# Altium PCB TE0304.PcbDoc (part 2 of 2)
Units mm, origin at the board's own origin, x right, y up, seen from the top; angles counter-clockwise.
Board outline 115 x 73 mm, 4 copper layers (L 01 (Top), L 02, L 03, L 04 (Bot)), stack 1.564 mm thick; 95 components, 174 nets, 553 pads, 126 vias.
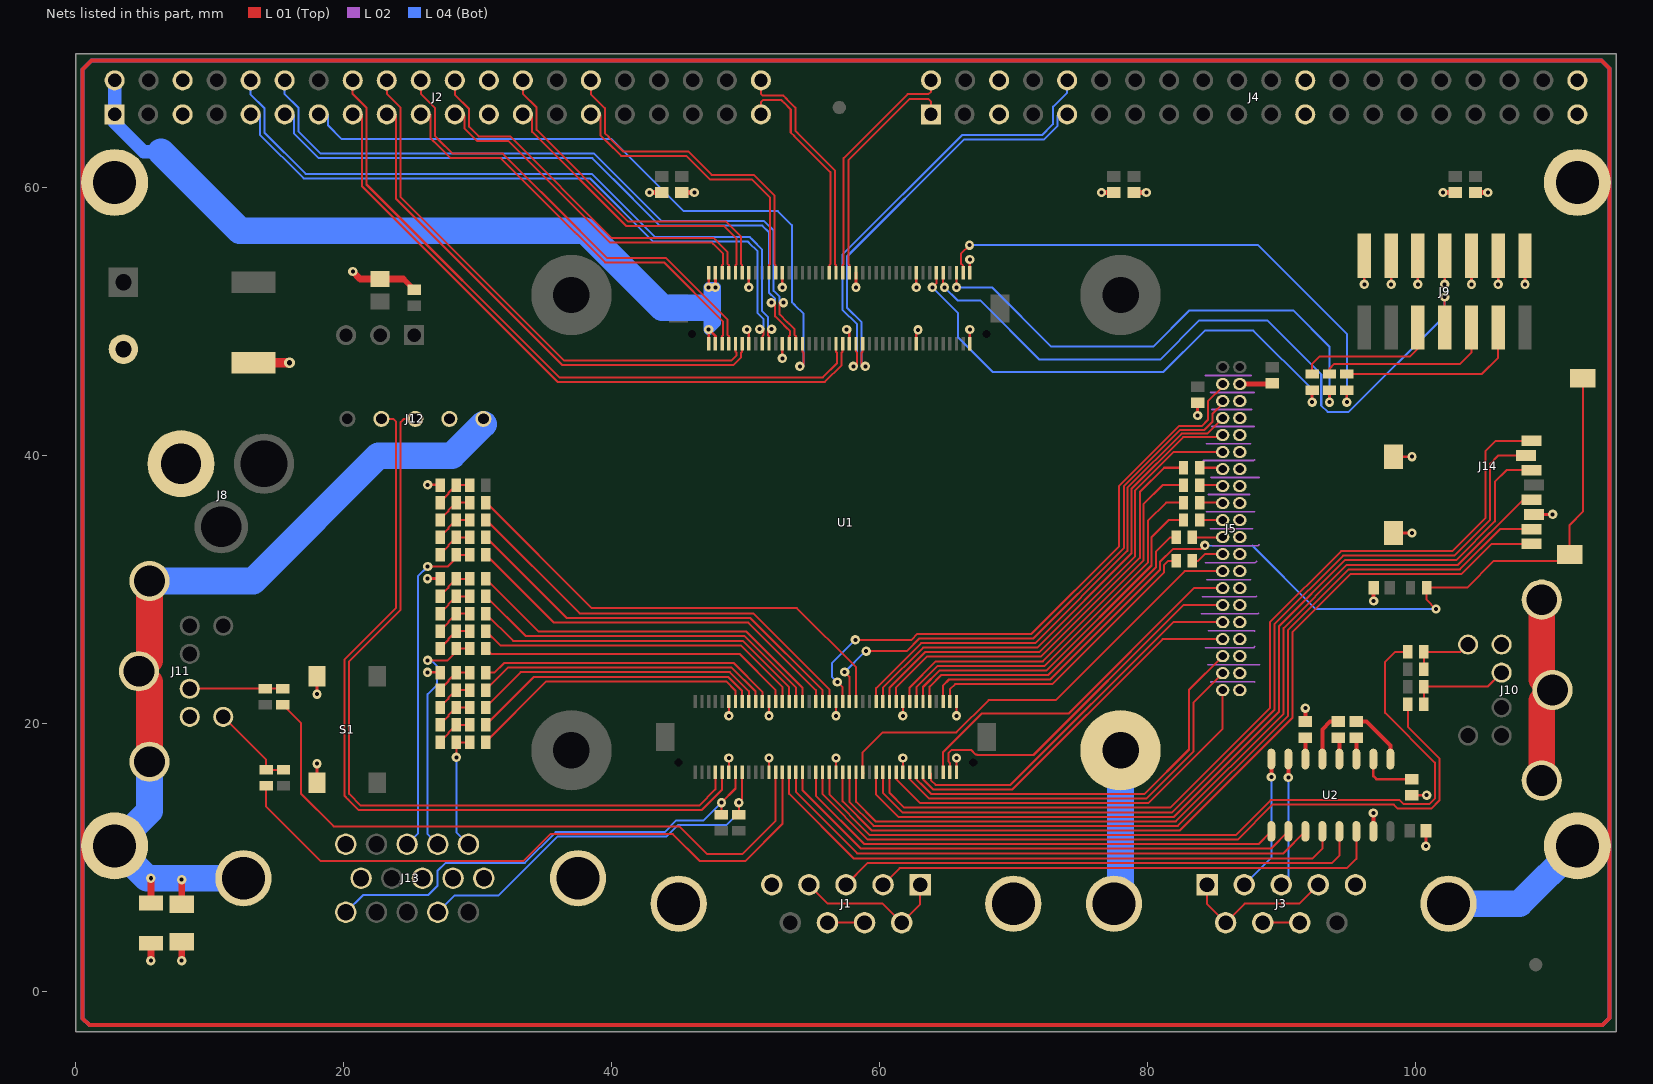
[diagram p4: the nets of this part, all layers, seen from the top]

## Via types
v1: diameter 0.7, hole 0.3, L 01 (Top) to L 04 (Bot), 124 vias
v2: diameter 0.8, hole 0.4, L 01 (Top) to L 04 (Bot), 2 vias

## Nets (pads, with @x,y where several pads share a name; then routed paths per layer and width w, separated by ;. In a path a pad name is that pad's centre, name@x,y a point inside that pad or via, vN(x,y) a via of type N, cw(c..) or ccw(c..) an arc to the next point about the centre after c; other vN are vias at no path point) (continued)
B0_L20_P: J2.13 U1.J4-29 | length 52.4
  L 01 (Top) w0.15: v1(54.05,46.675) 54.33,46.675 54.33,47.695 54.25,47.775 U1.J4-29@54.25,48.35
  L 04 (Bot) w0.15: J2.13@18.13,65.48 18.82,65.48 18.825,65.485 18.825,65.48 18.825,64.659 19.824,63.66 39.984,63.66 43.085,60.559 43.184,60.46 45.384,58.26 52.409,58.26 53.46,57.209 53.46,51.459 53.585,51.334 53.684,51.235 54.33,50.589 54.33,46.675 v1(54.05,46.675)
B0_L21_N: J2.29 U1.J4-20 | length 22.5
  L 01 (Top) w0.15: J2.29@38.45,65.48 39.115,65.48 39.16,65.435 39.16,63.934 39.535,63.559 39.634,63.46 40.709,62.385 45.584,62.385 47.334,60.635 50.459,60.635 51.83,59.264 51.83,54.305 51.75,54.225 U1.J4-20@51.75,53.65
B0_L21_P: J2.30 U1.J4-22 | length 24.8
  L 01 (Top) w0.15: J2.30@38.45,68.02 38.45,67 39.5,65.95 39.5,64.075 39.775,63.8 39.875,63.7 40.85,62.725 45.725,62.725 47.475,60.975 50.6,60.975 52.17,59.405 52.17,54.305 52.25,54.225 U1.J4-22@52.25,53.65
B0_L23_N: J2.11 U1.J4-25 | length 50.2
  L 01 (Top) w0.15: v1(51.93,51.429) 52.21,51.429 52.21,50.409 52.885,49.734 52.984,49.635 53.33,49.289 53.33,49.005 53.25,48.925 U1.J4-25@53.25,48.35
  L 04 (Bot) w0.15: J2.11@15.59,65.48 16.235,65.48 16.29,65.425 16.29,64.05 16.59,63.75 16.69,63.65 18.13,62.21 38.559,62.21 41.56,59.209 41.659,59.11 43.594,57.175 51.25,57.175 51.75,56.675 51.75,52.175 52.21,51.715 52.21,51.429 v1(51.93,51.429)
B0_L23_P: J2.12 U1.J4-27 | length 52.5
  L 01 (Top) w0.15: v1(52.83,51.429) 52.55,51.429 52.55,50.55 53.125,49.975 53.225,49.875 53.67,49.43 53.67,49.005 53.75,48.925 U1.J4-27@53.75,48.35
  L 04 (Bot) w0.15: J2.12@15.59,68.02 15.59,67 16.63,65.96 16.63,64.191 16.831,63.99 16.93,63.891 18.271,62.55 38.7,62.55 41.8,59.45 41.9,59.35 43.735,57.515 51.391,57.515 52.09,56.816 52.09,52.316 52.55,51.856 52.55,51.429 v1(52.83,51.429)
B0_L24_N: J2.9 U1.J4-17 | length 50.4
  L 01 (Top) w0.15: U1.J4-17@51.25,48.35 51.25,48.925 51.33,49.005 v1@51.33,49.45
  L 04 (Bot) w0.15: J2.9@13.05,65.48 13.735,65.48 13.74,65.475 13.74,63.975 17.005,60.71 38.384,60.71 43.119,55.975 50.175,55.975 50.25,55.9 50.9,55.25 50.9,50.65 51,50.55 51.05,50.5 51.33,50.22 51.33,49.45 v1(51.05,49.45)
B0_L24_P: J2.10 U1.J4-19 | length 52.6
  L 01 (Top) w0.15: v1@51.67,49.45 51.67,49.005 51.75,48.925 U1.J4-19@51.75,48.35
  L 04 (Bot) w0.15: J2.10@13.05,68.02 13.05,66.965 14.08,65.935 14.08,64.116 17.146,61.05 38.525,61.05 43.26,56.315 50.316,56.315 50.415,56.215 50.49,56.141 51.24,55.391 51.24,50.791 51.29,50.741 51.67,50.361 51.67,49.45 v1(51.95,49.45)
B1: R33.2 U1.J5-50 | length 35.4
  L 01 (Top) w0.15: R33.2@30.712,36.525 30.612,36.525 30.618,36.518 38.527,28.61 53.832,28.61 58.25,24.192 U1.J5-50@58.25,21.65
B2: R27.2 U1.J5-42 | length 31.8
  L 01 (Top) w0.15: R27.2@30.612,35.225 30.618,35.218 37.617,28.22 50.58,28.22 56.25,22.55 U1.J5-42@56.25,21.65
B3: R20.2 U1.J5-40 | length 30.7
  L 01 (Top) w0.15: R20.2@30.612,33.925 30.618,33.918 36.657,27.88 50.351,27.88 55.75,22.481 U1.J5-40@55.75,21.65
B3_L01_N: J2.20 U1.J4-7 | length 34
  L 01 (Top) w0.15: J2.20@25.75,68.02 25.75,67.025 26.8,65.975 26.8,63.875 26.975,63.7 27.075,63.6 28.125,62.55 31.875,62.55 37.525,56.9 37.625,56.8 39.65,54.775 44.05,54.775 48.67,50.155 48.67,49.005 48.75,48.925 U1.J4-7@48.75,48.35
B3_L01_P: J2.19 U1.J4-5 | length 31.7
  L 01 (Top) w0.15: J2.19@25.75,65.48 26.45,65.48 26.46,65.49 26.46,65.48 26.46,63.734 26.735,63.459 26.834,63.36 27.984,62.21 31.734,62.21 37.285,56.659 37.384,56.56 39.509,54.435 43.909,54.435 48.33,50.014 48.33,49.005 48.25,48.925 U1.J4-5@48.25,48.35
B3_L02_N: J2.17 U1.J4-11 | length 39.1
  L 01 (Top) w0.15: J2.17@23.21,65.48 23.845,65.48 23.9,65.425 23.9,59.169 36.294,46.775 49.1,46.775 49.2,46.875 49.3,46.975 49.67,47.345 49.67,47.695 49.75,47.775 U1.J4-11@49.75,48.35
B3_L02_P: J2.18 U1.J4-9 | length 40.3
  L 01 (Top) w0.15: J2.18@23.21,68.02 23.21,67.015 24.24,65.985 24.24,59.31 36.435,47.115 48.959,47.115 49.059,47.215 49.33,47.486 49.33,47.695 49.25,47.775 U1.J4-9@49.25,48.35
B3_L03_N: J2.25 U1.J4-10 | length 23.2
  L 01 (Top) w0.15: J2.25@33.37,65.48 34.05,65.48 34.06,65.49 34.06,65.48 34.06,64.184 41.109,57.135 48.409,57.135 49.33,56.214 49.33,54.305 49.25,54.225 U1.J4-10@49.25,53.65
B3_L03_P: J2.26 U1.J4-12 | length 25.4
  L 01 (Top) w0.15: J2.26@33.37,68.02 33.37,67.03 34.4,66 34.4,64.325 41.25,57.475 48.55,57.475 49.67,56.355 49.67,54.305 49.75,54.225 U1.J4-12@49.75,53.65
B3_L07_N: J2.22 U1.J4-8 | length 28.7
  L 01 (Top) w0.15: J2.22@28.29,68.02 28.29,66.96 29.35,65.9 29.35,64.575 29.375,64.55 29.475,64.45 30.075,63.85 32.425,63.85 40.025,56.25 47.625,56.25 47.725,56.15 47.825,56.05 48.67,55.205 48.67,54.305 48.75,54.225 U1.J4-8@48.75,53.65
B3_L07_P: J2.21 U1.J4-6 | length 26.4
  L 01 (Top) w0.15: J2.21@28.29,65.48 28.97,65.48 29.01,65.44 29.01,64.434 29.135,64.309 29.234,64.21 29.934,63.51 32.284,63.51 39.884,55.91 47.484,55.91 ; 47.485,55.909 47.584,55.81 48.33,55.064 48.33,54.305 48.25,54.225 U1.J4-6@48.25,53.65
B4: R14.2 U1.J5-38 | length 29.7
  L 01 (Top) w0.15: R14.2@30.612,32.625 30.618,32.618 35.697,27.54 50.21,27.54 55.25,22.5 U1.J5-38@55.25,21.65
BLUE: J13.3 R14.1 R17.1 | length 24.8
  L 01 (Top) w0.15: v1(26.262,31.725) 27.762,31.725 R17.1@28.424,32.387 ; R17.1@28.4,32.6 R14.1@29.4,32.6 R14.1@29.4,32.575
  L 04 (Bot) w0.15: J13.3@24.73,10.99 25.525,11.785 25.525,30.988 v1(26.262,31.725)
DOUT0: J5.30 U1.J5-60 | length 36.1
  L 01 (Top) w0.15: U1.J5-60@60.75,21.65 60.75,22.681 63.399,25.33 71.914,25.33 79.087,32.502 79.087,37.409 81.947,40.27 J5.30@85.63,40.27
DOUT1: J5.32 U1.J5-58 | length 37
  L 01 (Top) w0.15: U1.J5-58@60.25,21.65 60.25,22.662 63.258,25.67 71.773,25.67 78.817,32.713 78.817,37.521 82.676,41.38 85.47,41.38 J5.32@85.63,41.54 J5.32@85.609,41.54
DOUT2: J5.34 U1.J5-56 | length 38
  L 01 (Top) w0.15: U1.J5-56@59.75,21.65 59.75,22.642 63.118,26.01 71.633,26.01 78.51,32.887 78.51,37.596 82.564,41.65 84.47,41.65 J5.34@85.63,42.81
DOUT3: J5.38 U1.J5-46 | length 44.6
  L 01 (Top) w0.15: v1(56.85,23.1) 57.25,22.7 U1.J5-46@57.25,21.65 ; v1(58.2,26.25) 62.396,26.25 62.836,26.69 71.351,26.69 77.9,33.239 77.9,37.75 82.35,42.2 84.058,42.2 84.525,42.667 84.525,44.057 85.63,45.162 J5.38@85.63,45.35
  L 04 (Bot) w0.15: v1(56.85,23.1) 56.45,23.5 56.45,24.5 v1(58.2,26.25)
DOUT4: J5.36 U1.J5-48 | length 42.1
  L 01 (Top) w0.15: v1(57.4,23.85) 57.75,23.5 U1.J5-48@57.75,21.65 ; v1(59,25.4) 62.027,25.4 62.977,26.35 71.492,26.35 78.24,33.098 78.24,37.708 82.462,41.93 84.269,41.93 84.865,42.526 84.865,43.127 85.63,43.892 J5.36@85.63,44.08
  L 04 (Bot) w0.15: v1(57.4,23.85) 58.95,25.4 v1(59,25.4)
DOUT5: J5.2 U1.J5-61 | length 30.8
  L 01 (Top) w0.15: U1.J5-61@61.25,16.35 61.25,15.85 63.045,14.055 80.064,14.055 85.63,19.621 J5.2@85.63,22.49
DOUT6: J5.4 U1.J5-65 | length 30.5
  L 01 (Top) w0.15: U1.J5-65@62.25,16.35 62.25,15.85 63.705,14.395 79.923,14.395 83.45,17.922 83.45,21.58 J5.4@85.63,23.76
DOUT7: J5.6 U1.J5-67 | length 30.7
  L 01 (Top) w0.15: U1.J5-67@62.75,16.35 62.75,15.85 63.3,15.3 63.319,15.3 63.884,14.735 79.782,14.735 83.11,18.063 83.11,22.51 J5.6@85.63,25.03
DOUT8: J5.8 U1.J5-69 | length 27.9
  L 01 (Top) w0.15: U1.J5-69@63.25,16.35 63.25,15.85 64.025,15.075 69.925,15.075 81.15,26.3 J5.8@85.63,26.3
DOUT9: J5.10 U1.J5-71 | length 27.6
  L 01 (Top) w0.15: U1.J5-71@63.75,16.35 63.86,16.24 63.86,15.74 64.185,15.415 69.784,15.415 81.939,27.57 J5.10@85.63,27.57
EXPOSURE: R47.2 U1.J5-72 | length 24.8
  L 01 (Top) w0.15: U1.J5-72@63.75,21.65 63.75,22.75 64.63,23.63 72.618,23.63 80.64,31.652 80.64,32.84 81.7,33.9 R47.2@82.15,33.9
FGND: C15.1 H1.1 H2.1 H3.1 H4.1 J1.S1 J1.S2 J3.S1 J3.S2 J10.S1 J10.S2 J10.S3 J11.S1 J11.S2 J11.S3 J12.5 J13.S1 J13.S2 R4.1 U1.2 | length 844.1
  L 01 (Top) w0.3: 0.5,-2.008 0.5,10.87 0.5,60.4 0.5,68.825 1.175,69.5 113.9,69.5 114.5,68.9 114.5,60.4 114.5,10.87 114.5,-2 113.992,-2.508 1,-2.508 0.5,-2.008
  L 01 (Top) w0.5: R4.1@5.6,6.6 v1(5.6,8.45) ; C15.1@7.9,6.5 v1(7.9,8.35)
  L 01 (Top) w2: J11.S3@5.5,17.15 5.5,23.1 J11.S2@4.7,23.9 5.5,24.7 J11.S1@5.5,30.65 ; J10.S1@109.45,15.75 109.45,21.7 J10.S2@110.25,22.5 109.45,23.3 J10.S3@109.45,29.25
  L 04 (Bot) w0.3: 0.5,-2.008 0.5,10.87 0.5,60.4 0.5,68.825 1.175,69.5 113.9,69.5 114.5,68.9 114.5,60.4 114.5,10.87 114.5,-2 113.992,-2.508 1,-2.508 0.5,-2.008
  L 04 (Bot) w2: H1.1@2.89,10.87 5.31,8.45 v1(5.6,8.45) 7.9,8.45 J13.S2@12.505,8.45 ; H1.1@2.995,10.975 5.5,13.48 J11.S3@5.5,17.15 ; J11.S1@5.5,30.65 13.241,30.65 22.591,40 28.074,40 J12.5@30.43,42.356 ; J3.S2@77.505,6.55 78,7.045 U1.2@78,18 ; J3.S1@102.495,6.55 107.79,6.55 H2.1@112.11,10.87
FPGA_RXD-DCE: U1.J5-29 U2.12 | length 45
  L 01 (Top) w0.15: U1.J5-29@53.25,16.35 53.25,14.75 58.06,9.94 92.34,9.94 93.065,10.665 U2.12@93.065,11.95
FPGA_RXD-DTE: U1.J5-37 U2.9 | length 37.6
  L 01 (Top) w0.15: U1.J5-37@55.25,16.35 55.25,14.625 58.88,10.995 88.3,10.995 U2.9@89.255,11.95
FPGA_TXD-DCE: U1.J5-31 U2.11 | length 42.1
  L 01 (Top) w0.15: U1.J5-31@53.75,16.35 53.75,14.9 58.335,10.315 90.164,10.315 91.795,11.946 U2.11@91.795,11.95
FPGA_TXD-DTE: U1.J5-33 U2.10 | length 39.9
  L 01 (Top) w0.15: U1.J5-33@54.25,16.35 54.25,15.025 58.62,10.655 89.234,10.655 90.525,11.946 U2.10@90.525,11.95
FRAME_VALID: J5.14 U1.J5-75 | length 27.5
  L 01 (Top) w0.15: U1.J5-75@64.75,16.35 64.75,17.875 67.625,20.75 74.119,20.75 83.479,30.11 J5.14@85.63,30.11
G0: R40.2 U1.J5-34 | length 28.1
  L 01 (Top) w0.15: R40.2@30.6,30.825 30.612,30.812 34.565,26.86 50.072,26.86 54.25,22.682 U1.J5-34@54.25,21.65
G1: R34.2 U1.J5-32 | length 27
  L 01 (Top) w0.15: R34.2@30.6,29.525 30.612,29.512 33.605,26.52 49.932,26.52 53.75,22.702 U1.J5-32@53.75,21.65
G2: R28.2 U1.J5-30 | length 26
  L 01 (Top) w0.15: R28.2@30.6,28.225 30.612,28.212 32.645,26.18 49.791,26.18 53.25,22.721 U1.J5-30@53.25,21.65
G3: R21.2 U1.J5-28 | length 25
  L 01 (Top) w0.15: R21.2@30.6,26.925 30.612,26.912 31.685,25.84 49.65,25.84 52.75,22.74 U1.J5-28@52.75,21.65
G4: R15.2 U1.J5-26 | length 23.8
  L 01 (Top) w0.15: R15.2@30.6,25.625 30.612,25.612 31.025,25.2 49.55,25.2 52.25,22.5 U1.J5-26@52.25,21.65
GCLK_L11_N: J4.2 U1.J4-42 | length 18
  L 01 (Top) w0.15: U1.J4-42@57.25,53.65 57.25,54.225 57.33,54.305 57.33,62.211 62.109,66.99 63.65,66.99 63.85,67.19 J4.2@63.85,68.02
GCLK_L11_P: J4.1 U1.J4-44 | length 17.6
  L 01 (Top) w0.15: U1.J4-44@57.75,53.65 57.75,54.225 57.67,54.305 57.67,62.07 62.25,66.65 63.63,66.65 63.85,66.43 J4.1@63.85,65.48
GCLK_L12_N: J4.9 U1.J4-47 | length 32.2
  L 01 (Top) w0.15: U1.J4-47@58.75,48.35 58.75,47.775 58.67,47.695 58.67,46.675 v1(58.95,46.675)
  L 04 (Bot) w0.15: v1(58.95,46.675) 58.67,46.675 58.67,49.955 57.575,51.05 57.575,51.9 57.575,54.875 66.3,63.6 72.275,63.6 73.1,64.425 73.2,64.525 73.3,64.625 73.3,65.4 73.38,65.48 J4.9@74.01,65.48
GCLK_L12_P: J4.10 U1.J4-45 | length 34.5
  L 01 (Top) w0.15: v1(58.05,46.675) 58.33,46.675 58.33,47.695 58.25,47.775 U1.J4-45@58.25,48.35
  L 04 (Bot) w0.15: v1(58.05,46.675) 58.33,46.675 58.33,49.814 57.235,50.909 57.235,51.9 57.235,55.016 66.159,63.94 72.134,63.94 72.86,64.666 72.959,64.765 ; 72.96,64.766 72.96,66.06 74.01,67.11 J4.10@74.01,68.02
GCLK_L13_N: J2.15 U1.J4-41 | length 50
  L 01 (Top) w0.15: J2.15@20.67,65.48 21.345,65.48 21.36,65.465 21.36,60.109 35.959,45.51 55.916,45.51 57.17,46.764 57.17,47.695 57.25,47.775 U1.J4-41@57.25,48.35
GCLK_L13_P: J2.16 U1.J4-39 | length 51.2
  L 01 (Top) w0.15: J2.16@20.67,68.02 20.67,67.005 21.7,65.975 21.7,60.25 36.1,45.85 55.775,45.85 56.83,46.905 56.83,47.695 56.75,47.775 U1.J4-39@56.75,48.35
GCLK_L14_N: J2.39 U1.J4-38 | length 17
  L 01 (Top) w0.15: J2.39@51.15,65.48 51.15,66.4 51.3,66.55 52.675,66.55 52.75,66.475 52.85,66.375 53.375,65.85 53.375,64.125 53.625,63.875 53.725,63.775 56.33,61.17 56.33,54.305 56.25,54.225 U1.J4-38@56.25,53.65
GCLK_L14_P: J2.40 U1.J4-40 | length 17.6
  L 01 (Top) w0.15: J2.40@51.15,68.02 51.15,67.04 51.3,66.89 52.816,66.89 52.991,66.715 53.09,66.616 53.715,65.991 53.715,64.266 53.866,64.115 53.965,64.016 56.67,61.311 56.67,54.305 56.75,54.225 U1.J4-40@56.75,53.65
GND: C1.1 C2.2 C3.2 C4.2 C5.2 C6.2 C9.2 C10.2 C11.2 C12.2 C13.2 C14.2 C15.2 C16.2 C17.2 D1.2 J1.5 J2.5 J2.6 J2.23 J2.24 J3.5 J4.5 J4.6 J4.23 J4.24 J4.39 J4.40 J5.1 J5.3 J5.5 J5.7 J5.9 J5.11 J5.13 J5.15 J5.17 J5.19 J5.21 J5.23 J5.25 J5.27 J5.29 J5.31 J5.33 J5.35 J5.37 J7.2 J8.3 J9.1 J9.3 J9.5 J9.7 J9.9 J9.11 J9.13 J10.3 J11.3 J12.4 J13.5 J13.6 J13.7 J13.8 J13.10 J14.6 J14.10 R4.2 R42.2 R43.2 R44.2 S1.2 U1.J4-13 U1.J4-14 U1.J4-23 U1.J4-24 U1.J4-43 U1.J4-46 U1.J4-63 U1.J4-64 U1.J4-79 U1.J4-80 U1.J5-11 U1.J5-12 U1.J5-23 U1.J5-24 U1.J5-43 U1.J5-44 U1.J5-63 U1.J5-64 U1.J5-79 U1.J5-80 U2.15 | length 138.3
  L 01 (Top) w0.15: U1.J5-11@48.75,16.35 v1(48.75,17.425) ; v1(48.75,20.575) U1.J5-12@48.75,21.65 ; U1.J5-23@51.75,16.35 v1(51.75,17.425) ; v1(51.75,20.575) U1.J5-24@51.75,21.65 ; U1.J5-43@56.75,16.35 v1(56.75,17.425) ; v1(56.75,20.575) U1.J5-44@56.75,21.65 ; U1.J5-63@61.75,16.35 v1(61.75,17.425) ; v1(61.75,20.575) U1.J5-64@61.75,21.65 ; U1.J5-79@65.75,16.35 v1(65.75,17.425) ; v1(65.75,20.575) U1.J5-80@65.75,21.65
  L 01 (Top) w0.2: S1.2@18,15.575 v1(18,17) ; v1(18,22.2) S1.2@18,23.525 ; v1(26.25,23.825) R44.2@27.212,23.825 ; v1(26.25,30.825) R43.2@27.212,30.825 ; v1(26.262,37.825) R42.2@27.224,37.825 ; v1(50.1,49.425) 50.25,49.275 U1.J4-13@50.25,48.35 ; v1(50.25,52.575) U1.J4-14@50.25,53.65 ; v1(52.75,47.275) U1.J4-23@52.75,48.35 ; v1(52.75,52.575) U1.J4-24@52.75,53.65 ; U1.J4-43@57.75,48.35 v1@57.75,49.425 ; v1(58.25,52.575) U1.J4-46@58.25,53.65 ; U1.J4-63@62.75,48.35 v1@62.75,49.425 ; v1(62.75,52.575) U1.J4-64@62.75,53.65 ; U1.J4-79@66.75,48.35 v1(66.75,49.425) ; U1.J4-80@66.75,53.575 v1(66.75,54.65) ; v1(96.2,52.8) J9.13@96.2,54.935 ; v1(98.2,52.8) J9.11@98.2,54.935 ; J14.10@98.375,34.225 v1(99.765,34.225) ; J14.10@98.375,39.925 v1(99.765,39.925) ; C5.2@99.75,14.65 v1(100.85,14.65) ; v1(100.2,52.8) J9.9@100.2,54.935 ; v1(100.8,10.85) C6.2@100.8,12 ; v1(102.2,52.8) J9.7@102.2,54.935 ; v1(104.2,52.8) J9.5@104.2,54.935 ; v1(106.2,52.8) J9.3@106.2,54.935 ; v1(108.2,52.8) J9.1@108.2,54.935 ; J14.6@108.875,35.615 v1(110.265,35.615)
  L 01 (Top) w0.25: v1(83.75,43.005) C16.2@83.75,43.95
  L 01 (Top) w0.3: C11.2@91.8,20.15 v1(91.8,21.15) ; U2.15@96.875,11.95 v1(96.875,13.325) ; v1(96.9,29.15) C17.2@96.9,30.15
  L 01 (Top) w0.4: 24.45,53.2 C2.2@25.25,52.4 ; v1(42.825,59.65) C3.2@43.75,59.65 ; C4.2@45.25,59.65 v1(46.175,59.65) ; v1(76.575,59.65) C10.2@77.5,59.65 ; C9.2@79,59.65 v1(79.925,59.65) ; J5.37@86.955,45.405 J5.37@86.9,45.35 89.26,45.35 C12.2@89.315,45.405 ; v1(102.075,59.65) C13.2@103,59.65 ; C14.2@104.5,59.65 v1(105.425,59.65)
  L 01 (Top) w0.5: v1(5.6,2.3) R4.2@5.6,3.6 ; v1(7.9,2.3) C15.2@7.9,3.7 ; v1(20.675,53.75) 21.225,53.2 C1.1@22.7,53.2 24.45,53.2
  L 01 (Top) w0.7: D1.2@13.25,46.95 v2(15.95,46.95)
  L 02 w0.12: 84.04,28.21 88.26,28.21 88.3,28.25 ; 84.12,29.48 88.13,29.48 88.15,29.5 ; 84.19,39.64 87.955,39.64 88.015,39.7 ; 84.33,25.67 87.935,25.67 88.015,25.75 ; 84.33,32.02 88.07,32.02 88.15,32.1 ; 84.34,45.99 87.74,45.99 87.75,46 ; 84.4,40.9 87.7,40.9 ; 84.42,35.82 87.995,35.82 88.015,35.8 ; 84.45,30.75 87.7,30.75 ; 84.515,24.4 88.4,24.4 ; 84.545,26.93 87.985,26.93 88.015,26.9 ; 84.565,37.1 87.65,37.1 ; 84.7,34.55 87.85,34.55 ; 84.7,44.75 84.73,44.72 87.985,44.72 ; 84.75,23.1 84.77,23.12 87.995,23.12 88.015,23.1 ; 84.75,38.4 84.78,38.37 88.37,38.37 ; 84.8,42.2 84.82,42.18 87.995,42.18 ; 84.8,43.45 87.8,43.45 ; 84.871,33.29 88.29,33.29 88.35,33.35
  other v1: 95.2,8.15 62.875,49.4 57.55,49.425
GREEN: J13.2 R15.1 R18.1 | length 18.5
  L 01 (Top) w0.15: v1(26.262,24.725) 27.762,24.725 28.412,25.375 R18.1@28.412,25.6 ; R18.1@28.4,25.6 R18.1@28.412,25.6 ; R15.1@29.4,25.575 R15.1@29.4,25.6 R18.1@28.412,25.6
  L 04 (Bot) w0.15: v1(26.262,24.725) 26.525,24.725 26.975,24.275 26.975,22.913 26.262,22.2 26.262,11.748 J13.2@27.02,10.99
LINE_VALID: J5.12 U1.J5-77 | length 26.9
  L 01 (Top) w0.15: U1.J5-77@65.25,16.35 65.25,17.055 65.135,17.17 65.135,17.779 65.396,18.04 66.835,18.04 67.19,17.685 67.265,17.685 67.3,17.65 71.5,17.65 82.69,28.84 J5.12@85.63,28.84
NetC5_1: C5.1 U2.2 | length 4.2
  L 01 (Top) w0.2: U2.2@96.875,17.35 96.875,16.075 97.1,15.85 C5.1@99.75,15.85
NetC7_1: C7.1 U2.4 | length 1.5
  L 01 (Top) w0.3: U2.4@94.335,17.35 C7.1@94.335,18.865
NetC7_2: C7.2 U2.5 | length 3.6
  L 01 (Top) w0.3: U2.5@93.065,17.35 93.065,19.565 93.65,20.15 C7.2@94.25,20.15
NetC8_1: C8.1 U2.1 | length 4.3
  L 01 (Top) w0.3: C8.1@95.6,20.15 96.35,20.15 98.145,18.355 U2.1@98.145,17.35
NetC8_2: C8.2 U2.3 | length 1.6
  L 01 (Top) w0.3: U2.3@95.605,17.35 C8.2@95.605,18.945
NetC11_1: C11.1 U2.6 | length 1.6
  L 01 (Top) w0.3: U2.6@91.8,17.355 C11.1@91.8,18.95
NetJ1_1: J1.1 J1.4 J1.6 | length 11.5
  L 01 (Top) w0.15: J1.4@54.73,7.97 56.15,6.55 60.235,6.55 J1.6@61.655,5.13 63.04,6.515 J1.1@63.04,7.97
NetJ1_7: J1.7 J1.8 | length 2.8
  L 01 (Top) w0.15: J1.8@56.115,5.13 J1.7@58.885,5.13
NetJ3_1: J3.1 J3.4 J3.6 | length 11.5
  L 01 (Top) w0.15: J3.1@84.46,7.97 84.46,6.515 J3.6@85.845,5.13 87.265,6.55 91.35,6.55 J3.4@92.77,7.97
NetJ3_7: J3.7 J3.8 | length 2.8
  L 01 (Top) w0.15: J3.7@88.615,5.13 J3.8@91.385,5.13
NetJ5_18: J5.18 R46.1 | length 2.5
  L 01 (Top) w0.15: R46.1@83.35,32.15 83.8,32.15 84.3,32.65 J5.18@85.63,32.65
NetJ5_20: J5.20 R47.1 | length 2.3
  L 01 (Top) w0.15: R47.1@83.35,33.9 85.61,33.9 J5.20@85.63,33.92
NetJ5_22: J5.22 R48.1 | length 1.7
  L 01 (Top) w0.15: R48.1@83.9,35.2 85.62,35.2 J5.22@85.63,35.19
NetJ5_24: J5.24 R49.1 | length 1.7
  L 01 (Top) w0.15: R49.1@83.9,36.5 85.59,36.5 J5.24@85.63,36.46
NetJ5_26: J5.26 R50.1 | length 1.8
  L 01 (Top) w0.15: R50.1@83.9,37.8 85.56,37.8 J5.26@85.63,37.73
NetJ5_28: J5.28 R51.1 | length 1.8
  L 01 (Top) w0.15: R51.1@83.9,39.1 85.53,39.1 J5.28@85.63,39
NetJ10_1: J10.1 R6.2 R7.1 | length 7.5
  L 01 (Top) w0.15: R7.1@100.65,21.45 R6.2@100.65,22.75 105.4,22.75 J10.1@106.45,23.8
NetJ10_5: J10.5 R5.2 R8.1 | length 5.1
  L 01 (Top) w0.15: R5.2@100.65,24.05 R8.1@100.65,25.35 103.4,25.35 J10.5@103.95,25.9 ; J10.5@103.95,25.35 J10.5@104.2,25.35
NetJ11_1: J11.1 R10.2 R11.1 | length 9.7
  L 01 (Top) w0.15: 11.225,22.6 J11.1@8.5,22.6 R10.2@14.15,22.6 R11.1@15.45,22.6
NetJ11_5: J11.5 R9.2 R12.1 | length 6.6
  L 01 (Top) w0.15: J11.5@11,20.5 14.2,17.3 R12.1@14.2,16.55 R9.2@15.5,16.55
NetR1_1: R1.1 U1.J4-70 | length 38.2
  L 01 (Top) w0.15: v1(63.95,52.575) 64.25,52.875 U1.J4-70@64.25,53.65
  L 01 (Top) w0.2: v1(92.3,44) R1.1@92.3,44.9
  L 04 (Bot) w0.15: v1(63.95,52.575) 65.875,50.65 65.875,48.825 68.45,46.25 81.2,46.25 84.287,49.337 87.913,49.337 92.3,44.95 v1(92.3,44)
NetR2_1: R2.1 U1.J4-76 | length 38
  L 01 (Top) w0.15: v1(65.75,52.575) U1.J4-76@65.75,53.65
  L 01 (Top) w0.2: v1(93.6,44) R2.1@93.6,44.9
  L 04 (Bot) w0.15: v1(65.75,52.575) 68.4,52.575 72.825,48.15 80.45,48.15 83.15,50.85 90.9,50.85 93.6,48.15 v1(93.6,44)
NetR3_1: R3.1 U1.J4-78 | length 39.3
  L 01 (Top) w0.15: U1.J4-78@66.25,53.65 66.25,54.175 66.075,54.35 66.075,55.075 v1(66.725,55.725)
  L 01 (Top) w0.2: v1(94.9,44) R3.1@94.9,44.9
  L 04 (Bot) w0.15: v1(66.725,55.725) 88.275,55.725 94.9,49.1 v1(94.9,44)
NetR17_2: R17.2 R20.1 R24.1 | length 2.8
  L 01 (Top) w0.15: R17.2@27.2,32.6 27.2,32.625 27.815,33.24 27.815,33.315 R24.1@28.4,33.9 R20.1@29.4,33.9
NetR18_2: R18.2 R21.1 R25.1 | length 2.8
  L 01 (Top) w0.15: R18.2@27.2,25.6 27.2,25.625 27.815,26.24 27.815,26.315 R25.1@28.4,26.9 R21.1@29.4,26.9
NetR19_2: R19.2 R22.1 R26.1 | length 2.8
  L 01 (Top) w0.15: R19.2@27.2,18.6 27.2,18.625 27.815,19.24 27.815,19.315 R26.1@28.4,19.9 R22.1@29.4,19.9
NetR24_2: R24.2 R27.1 R30.1 | length 2.8
  L 01 (Top) w0.15: R24.2@27.2,33.9 27.2,33.925 27.815,34.54 27.815,34.615 R30.1@28.4,35.2 R27.1@29.4,35.2
NetR25_2: R25.2 R28.1 R31.1 | length 2.8
  L 01 (Top) w0.15: R25.2@27.2,26.9 27.2,26.925 27.815,27.54 27.815,27.615 R31.1@28.4,28.2 R28.1@29.4,28.2
NetR26_2: R26.2 R29.1 R32.1 | length 2.8
  L 01 (Top) w0.15: R26.2@27.2,19.9 27.2,19.925 27.815,20.54 27.815,20.615 R32.1@28.4,21.2 R29.1@29.4,21.2
NetR30_2: R30.2 R33.1 R36.1 | length 2.8
  L 01 (Top) w0.15: R30.2@27.2,35.2 27.2,35.225 27.815,35.84 27.815,35.915 R36.1@28.4,36.5 R33.1@29.4,36.5
NetR31_2: R31.2 R34.1 R37.1 | length 2.8
  L 01 (Top) w0.15: R31.2@27.2,28.2 27.2,28.225 27.815,28.84 27.815,28.915 R37.1@28.4,29.5 R34.1@29.4,29.5
NetR32_2: R32.2 R35.1 R38.1 | length 2.8
  L 01 (Top) w0.15: R32.2@27.2,21.2 27.2,21.225 27.815,21.84 27.815,21.915 R38.1@28.4,22.5 R35.1@29.4,22.5
NetR36_2: R36.2 R39.1 R42.1 | length 2.8
  L 01 (Top) w0.15: R36.2@27.2,36.5 27.2,36.525 27.815,37.14 27.815,37.215 R42.1@28.4,37.8 R39.1@29.4,37.8
NetR37_2: R37.2 R40.1 R43.1 | length 2.8
  L 01 (Top) w0.15: R37.2@27.2,29.5 27.2,29.525 27.815,30.14 27.815,30.215 R43.1@28.4,30.8 R40.1@29.4,30.8
NetR38_2: R38.2 R41.1 R44.1 | length 2.8
  L 01 (Top) w0.15: R38.2@27.2,22.5 27.2,22.525 27.815,23.14 27.815,23.215 R44.1@28.4,23.8 R41.1@29.4,23.8
PIXCLK: J5.16 U1.J5-51 | length 34.1
  L 01 (Top) w0.15: U1.J5-51@58.815,16.285 U1.J5-51@58.75,16.35 58.75,17.85 60.25,19.35 65.744,19.35 68.144,21.75 73.15,21.75 82.78,31.38 J5.16@85.63,31.38
PS2_C1: R8.2 U1.J5-41 | length 63.2
  L 01 (Top) w0.15: U1.J5-41@56.25,16.35 56.25,14.706 59.281,11.675 86.594,11.675 89.199,14.28 98.845,14.28 99.14,13.985 101.055,13.985 101.465,14.395 101.465,17.085 97.75,20.8 97.75,24.6 98.5,25.35 R8.2@99.45,25.35
PS2_C2: R12.2 U1.J5-27 | length 48.5
  L 01 (Top) w0.15: R12.2@14.2,15.35 14.2,13.8 18.275,9.725 33.4,9.725 35.425,11.75 44.575,11.75 46.6,9.725 49.975,9.725 52.75,12.5 U1.J5-27@52.75,16.35
PS2_D1: R7.2 U1.J5-39 | length 58.7
  L 01 (Top) w0.15: U1.J5-39@55.75,16.35 55.75,14.725 59.14,11.335 86.735,11.335 89.34,13.94 98.4,13.94 98.695,13.645 101.196,13.645 101.805,14.254 101.805,17.395 99.45,19.75 R7.2@99.45,21.45
PS2_D2: R11.2 U1.J5-25 | length 49.1
  L 01 (Top) w0.15: R11.2@15.45,21.4 16.8,20.05 16.8,14.775 19.25,12.325 45.05,12.325 47.125,10.25 49.75,10.25 52.25,12.75 U1.J5-25@52.25,16.35
R0: R41.2 U1.J5-22 | length 22.6
  L 01 (Top) w0.15: R41.2@30.6,23.8 31.25,23.8 31.97,24.52 49.103,24.52 51.25,22.373 U1.J5-22@51.25,21.65
R1: R35.2 U1.J5-20 | length 22.3
  L 01 (Top) w0.15: R35.2@30.6,22.525 32.255,24.18 48.962,24.18 50.75,22.392 U1.J5-20@50.75,21.65
R2: R29.2 U1.J5-18 | length 22.1
  L 01 (Top) w0.15: R29.2@30.6,21.225 33.215,23.84 48.822,23.84 50.25,22.412 U1.J5-18@50.25,21.65
R3: R22.2 U1.J5-16 | length 21.9
  L 01 (Top) w0.15: R22.2@30.6,19.925 R22.2@30.6,19.9 30.6,19.887 30.607,19.893 34.203,23.49 48.691,23.49 49.75,22.431 U1.J5-16@49.75,21.65
R4: R16.2 U1.J5-14 | length 21.6
  L 01 (Top) w0.15: R16.2@30.6,18.625 35.125,23.15 48.55,23.15 49.25,22.45 U1.J5-14@49.25,21.65
RED: J13.1 R16.1 R19.1 | length 9
  L 01 (Top) w0.15: R19.1@28.4,18.6 R19.1@28.412,18.6 ; v1(28.412,17.475) R19.1@28.412,18.6 ; J13.1@29.3,10.98 J13.1@29.31,10.99 ; R16.1@29.4,18.6 R19.1@28.412,18.6
  L 04 (Bot) w0.15: v1(28.412,17.475) 28.412,11.868 J13.1@29.3,10.98
RXD-DCE: J1.3 U2.13 | length 39.5
  L 01 (Top) w0.15: J1.3@57.5,7.97 59.13,9.6 93.8,9.6 94.335,10.135 U2.13@94.335,11.95
RXD-DTE: J3.2 U2.8 | length 10.2
  L 01 (Top) w0.3: v1(89.255,16.005) U2.8@89.255,17.35
  L 04 (Bot) w0.15: J3.2@87.23,7.97 89.255,9.995 v1(89.255,16.005)
SCLK: R48.2 U1.J5-70 | length 26.9
  L 01 (Top) w0.15: U1.J5-70@63.25,21.65 63.25,22.731 64.489,23.97 72.478,23.97 80.31,31.802 80.31,33.91 81.6,35.2 R48.2@82.7,35.2
SD_CLK: J14.5 U1.J5-49 | length 66.9
  L 01 (Top) w0.15: U1.J5-49@58.25,16.35 58.25,14.148 59.703,12.695 82.133,12.695 90.17,20.731 90.17,27.131 94.893,31.855 103.193,31.855 108.053,36.715 J14.5@108.675,36.715
SD_CMD: J14.3 U1.J5-55 | length 67.5
  L 01 (Top) w0.15: U1.J5-55@59.75,16.35 59.75,14.7 61.415,13.035 81.993,13.035 89.83,20.872 89.83,27.272 94.753,32.195 103.053,32.195 105.95,35.092 105.95,38.05 106.815,38.915 J14.3@108.675,38.915
SD_D0: J14.7 U1.J5-47 | length 66.8
  L 01 (Top) w0.15: U1.J5-47@57.75,16.35 57.75,14.167 59.562,12.355 82.274,12.355 90.51,20.59 90.51,26.99 95.034,31.515 103.334,31.515 106.334,34.515 J14.7@108.675,34.515
SD_D1: J14.8 U1.J5-45 | length 67.1
  L 01 (Top) w0.15: U1.J5-45@57.25,16.35 57.25,14.187 59.422,12.015 82.415,12.015 90.85,20.45 90.85,26.85 95.175,31.175 103.475,31.175 105.715,33.415 J14.8@108.675,33.415
SD_D2: J14.1 U1.J5-59 | length 67.9
  L 01 (Top) w0.15: U1.J5-59@60.75,16.35 60.75,14.821 61.856,13.715 81.711,13.715 89.15,21.154 89.15,27.554 94.471,32.875 102.771,32.875 105.26,35.364 105.26,40.36 106.015,41.115 J14.1@108.675,41.115
SD_D3: J14.2 U1.J5-57 | length 67.4
  L 01 (Top) w0.15: U1.J5-57@60.25,16.35 60.25,14.84 61.715,13.375 81.852,13.375 89.49,21.013 89.49,27.413 94.612,32.535 102.912,32.535 105.6,35.223 105.6,39.4 106.215,40.015 J14.2@108.275,40.015
SD_SW: J14.9 R45.1 U1.J5-76 | length 71.8
  L 01 (Top) w0.15: U1.J5-76@64.75,21.65 64.75,22.85 65.19,23.29 72.759,23.29 80.935,31.465 80.935,32.06 81.924,33.05 84.05,33.05 v1(84.3,33.3) ; v1(101.55,28.55) 100.85,29.25 R45.1@100.85,30.15 103.875,30.15 105.875,32.15 111.05,32.15 J14.9@111.525,32.625 111.525,34.825 112.525,35.825 J14.9@112.525,45.775
  L 04 (Bot) w0.12: v1(84.3,33.3) 84.31,33.29 87.85,33.29
  L 04 (Bot) w0.15: 87.85,33.29 92.59,28.55 v1(101.55,28.55)
SDATA: R50.2 U1.J5-66 | length 30.2
  L 01 (Top) w0.15: U1.J5-66@62.25,21.65 62.25,22.692 64.208,24.65 72.196,24.65 79.71,32.164 79.71,36.378 81.132,37.8 R50.2@82.7,37.8
STFRM_OUT: R49.2 U1.J5-68 | length 28.6
  L 01 (Top) w0.15: U1.J5-68@62.75,21.65 62.75,22.712 64.348,24.31 72.337,24.31 80.04,32.013 80.04,35.14 81.4,36.5 R49.2@82.7,36.5
STLN_OUT: R46.2 U1.J5-78 | length 22.1
  L 01 (Top) w0.15: U1.J5-78@65.25,21.65 65.25,22.55 65.65,22.95 72.9,22.95 81.25,31.3 81.25,31.85 81.55,32.15 R46.2@82.15,32.15
SYSCLK: R51.2 U1.J5-62 | length 32.2
  L 01 (Top) w0.15: U1.J5-62@61.25,21.65 61.25,22.7 63.54,24.99 72.055,24.99 79.44,32.375 79.44,37.287 81.253,39.1 R51.2@82.7,39.1
TCK: J9.6 R2.2 | length 13.4
  L 01 (Top) w0.15: R2.2@93.6,46.1 93.6,46.5 93.95,46.85 103.35,46.85 104.2,47.7 J9.6@104.2,49.565
TDI: J9.10 R1.2 | length 10.7
  L 01 (Top) w0.15: R1.2@92.3,46.1 92.3,46.85 92.85,47.4 99.6,47.4 100.2,48 J9.10@100.2,49.565
TDO: J9.8 U1.J4-72 | length 52.7
  L 01 (Top) w0.15: v1@64.75,52.575 U1.J4-72@64.75,53.65 ; J9.8@102.2,49.565 v1(102.2,51.85)
  L 04 (Bot) w0.15: v1(64.85,52.575) 65.825,51.6 67.525,51.6 71.948,47.177 80.952,47.177 83.875,50.1 88.95,50.1 92.985,46.065 92.985,43.745 93.465,43.265 95.035,43.265 102.2,50.43 v1(102.2,51.85)
TMS: J9.4 R3.2 | length 14
  L 01 (Top) w0.15: R3.2@94.9,46.1 104.975,46.1 106.2,47.325 J9.4@106.2,49.565
TXD-DCE: J1.2 U2.14 | length 38.7
  L 01 (Top) w0.15: J1.2@60.27,7.97 61.5,9.2 81.45,9.2 ; 81.95,9.2 81.45,9.2 ; U2.14@95.605,11.95 95.605,9.905 94.9,9.2 81.45,9.2
TXD-DTE: J3.3 U2.7 | length 10.4
  L 01 (Top) w0.3: v1(90.525,15.975) U2.7@90.525,17.35
  L 04 (Bot) w0.15: J3.3@89.78,7.97 J3.3@90,7.97 ; v1(90.525,15.975) 90.525,8.495 J3.3@90,7.97 ; J3.3@90.6,7.97 J3.3@90,7.97
USB_D_N: J12.2 U1.J5-9 | length 61.3
  L 01 (Top) w0.15: J12.2@22.81,42.75 23.7,42.75 23.91,42.54 23.91,41.417 23.91,39.32 23.91,28.641 20.06,24.791 20.06,14.75 20.06,14.609 20.159,14.51 20.35,14.319 21.134,13.535 46.71,13.535 48.25,15.075 U1.J5-9@48.25,16.35
USB_D_P: J12.3 U1.J5-7 | length 60
  L 01 (Top) w0.15: J12.3@25.35,42.75 24.5,42.75 24.25,42.5 24.25,41.521 24.25,39.39 24.25,28.5 20.4,24.65 20.4,14.75 21.275,13.875 46.544,13.875 47.75,15.081 U1.J5-7@47.75,16.35
VCCIO0: J2.1 J2.2 U1.J4-1 U1.J4-2 U1.J4-3 U1.J4-4 | length 64.4
  L 01 (Top) w0.2: U1.J4-1@47.25,48.35 v1(47.25,49.425) 47.75,48.925 U1.J4-3@47.75,48.35 ; v1(47.25,52.575) U1.J4-2@47.25,53.65 ; v1(47.75,52.575) U1.J4-4@47.75,53.65
  L 04 (Bot) w0.8: v1@47.71,52.575 v1(47.25,52.575) v1(47.25,49.425) 47.75,49.925 47.75,50.35 v1(47.75,52.575)
  L 04 (Bot) w1: J2.2@2.89,68.02 J2.1@2.89,65.48 2.89,64.86 5.057,62.693 6.343,62.693
  L 04 (Bot) w2: 6.343,62.693 12.236,56.8 38.027,56.8 43.777,51.05 46.925,51.05
VGA_SCL: J13.15 R23.1 U1.J5-13 | length 35.7
  L 01 (Top) w0.15: R23.1@48.25,13.25 R23.1@48.2,13.2 v1(48.2,14.1) 49.25,15.15 U1.J5-13@49.25,16.35
  L 04 (Bot) w0.15: J13.15@20.15,5.91 21.44,7.2 26.3,7.2 27,7.9 27,9 27.6,9.6 33.519,9.6 35.815,11.896 43.953,11.896 44.828,12.77 46.87,12.77 v1(48.2,14.1)
VGA_SDA: J13.12 R13.1 U1.J5-15 | length 29.6
  L 01 (Top) w0.15: R13.1@49.5,13.2 v1(49.5,14.1) 49.75,14.35 U1.J5-15@49.75,16.35
  L 04 (Bot) w0.15: J13.12@27.02,5.91 28.26,7.15 31.55,7.15 35.956,11.556 44.094,11.556 44.968,12.43 48.58,12.43 49.5,13.35 v1(49.5,14.1)
pads on no net: J1.9 J3.9 J8.2 J9.12 J9.14 J10.2 J10.6 J11.2 J11.6 J13.4 J13.9 J13.11 PM1.0 PM2.0 PM3.0 U1.1 U1.3 U1.4 U1.A U1.B U1.G1 U1.G2 U1.J5-8 U1.J5-10 U1.J5-17
copper on no net: | length 88
  L 01 (Top) w0.15: 111.75,-1.65 111.75,7.35 113.75,7.35 113.75,-1.65 111.75,-1.65
  L 02 w0.15: 111.75,-1.65 113.75,-1.65 113.75,7.35 111.75,7.35 111.75,-1.65
  L 03 w0.15: 111.75,-1.65 113.75,-1.65 113.75,7.35 111.75,7.35 111.75,-1.65
  L 04 (Bot) w0.15: 111.75,-1.65 113.75,-1.65 113.75,7.35 111.75,7.35 111.75,-1.65

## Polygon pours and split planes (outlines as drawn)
GND on L 02 "GND" (solid, remove dead copper, pour order 1000): 1,69 1,-2 114,-2 114,69 107,69
GND on L 03 "L 03-GND" (solid, remove dead copper, pour order 1001): 7.5,43 81,43 86.35,48.5 90.5,48.5 90.5,43 106,43 106,69.5 7.5,69.54
3.3V on L 03 "L 03-3,3" (solid, remove dead copper, pour order 1000): 7,69.5 0.5,69.5 0.5,-2.5 114.5,-2.5 114.5,69.5 106.5,69.5 106.5,42.5 90,42.5 90,48 86.5,48 81,42.5 7,42.5
3.3V on L 04 (Bot) "L4 3.3" (solid, remove dead copper, pour order 1001): 42.5,69 42.5,62.725 45.725,59.5 48,59.5 53,59.5 54,58.5 54.45,58.05 54.45,52.2 55.5,51.15 55.5,41 59,41 59,45 56.335,47.665 56.335,50.193 56.335,60.665 54.5,62.5 54.378,62.622 47.178,62.622 45.3,64.5 45,64.5 45,69

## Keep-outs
Keep-Out Layer:
  the board outline again, w0.3

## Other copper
L 01 (Top):
  rectangle net FGND: 43.8,-2.508 46.25,6.6
  rectangle net FGND: 68.79,-2.508 71.24,6.6
  rectangle net FGND: 76.3,-2.508 78.75,6.6
  rectangle net FGND: 101.29,-2.508 103.74,6.6
  rectangle net FGND: 11.3,-2.508 13.75,8.5
  rectangle net FGND: 36.29,-2.508 38.74,8.5
  region net FGND: 0.5,25.105 0.5,22.655 4.75,22.655 4.75,25.105
  region net FGND: 114.45,21.295 114.45,23.745 110.2,23.745 110.2,21.295
  text "J4" at 106.5,61.95 h1
  text "J2" at 11.6,61.6 h1
  text "+5V" at 12.05,57.65 h1
  text "J7" at 9.85,55.1 h1
  text "EXT" at 19.75,54.5 h1 r90
  text "J9" at 87.95,48.9 h1
  text "USB" at 28.9,47.45 h1 r90
  text "J8" at 17.35,36.35 h1
  text "TE0304-00" at 54.75,29.15 h1
  text "J11" at 13.55,26.85 h1
  text "J10" at 96.7,26.7 h1
  text "RESET" at 20.3,26.15 h1 r90
  text "J1" at 53.15,10.35 h1
  text "L1" at 112.25,6.85 h1 r270
  text "J3" at 106.75,6.1 h1
  text "J13" at 3.35,-1 h1
L 02:
  text "L2" at 112.25,4.85 h1 r270
L 03:
  text "L3" at 112.25,2.85 h1 r270
L 04 (Bot):
  region net FGND: 0.5,25.105 0.5,22.655 4.75,22.655 4.75,25.105
  rectangle net FGND: 36.29,-2.508 38.74,8.5
  rectangle net FGND: 11.3,-2.508 13.75,8.5
  rectangle net FGND: 101.29,-2.508 103.74,6.6
  rectangle net FGND: 76.3,-2.508 78.75,6.6
  rectangle net FGND: 68.79,-2.508 71.24,6.6
  rectangle net FGND: 43.8,-2.508 46.25,6.6
  region net FGND: 114.45,21.295 114.45,23.745 110.2,23.745 110.2,21.295
  text "L4" at 112.25,-1.15 h1 r270

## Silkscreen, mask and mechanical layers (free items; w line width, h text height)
Top Solder:
  rectangle: 106.375,5.7 109.7,8
  rectangle: 60.625,31.8 73.75,42.75
  region: 45.7,42.85 45.7,31.9 54.05,31.9 54.05,42.85
  rectangle: 11.3,61.2 14.525,63.5
  rectangle: 106.125,61.5 109.5,63.85
  rectangle: 106.721,1.021 109.996,3.121
  rectangle: 2.9,-1.375 7.65,0.85
  region: 20.15,54.1 20.15,58.925 17.85,58.925 17.85,54.1
  region: 29.4,47.075 29.4,51.95 26.95,51.95 26.95,47.075
  rectangle: 96.4,26.225 101.025,28.65
  rectangle: 54.4,28.75 68.45,31.2
  region: 16.55,59.6 11.725,59.6 11.725,57.3 16.55,57.3
  region: 12.8,57.1 9.475,57.1 9.475,54.8 12.8,54.8
  region: 20.45,38.25 16.925,38.25 16.925,35.95 20.45,35.95
  region: 17.25,28.75 13.325,28.75 13.325,26.45 17.25,26.45
  region: 18.35,33.6 18.35,25.825 20.65,25.825 20.65,33.6
  rectangle: 53,10.05 55.45,12.35
  rectangle: 87.575,48.45 90.9,50.75
Boardumrandung:
  the board outline again, w0.01

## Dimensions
0,-3 to 37,52 on Dimension
0,-3 to 2.89,60.4 on Dimension
0,-3 to 37,18 on Dimension
0,-3 to 2.89,10.87 on Dimension
78,18 to 78,52 on Dimension
112.11,10.87 to 112.11,60.4 on Dimension
115,-3 to 115,70 on Dimension
0,70 to 112.11,60.4 on Dimension
0,70 to 78,52 on Dimension
0,70.259 to 37,52 on Dimension
0,70 to 2.89,60.4 on Dimension
37,18 to 78,18 on Dimension
2.89,10.87 to 112.11,10.87 on Dimension
0,-3 to 115,-3 on Dimension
